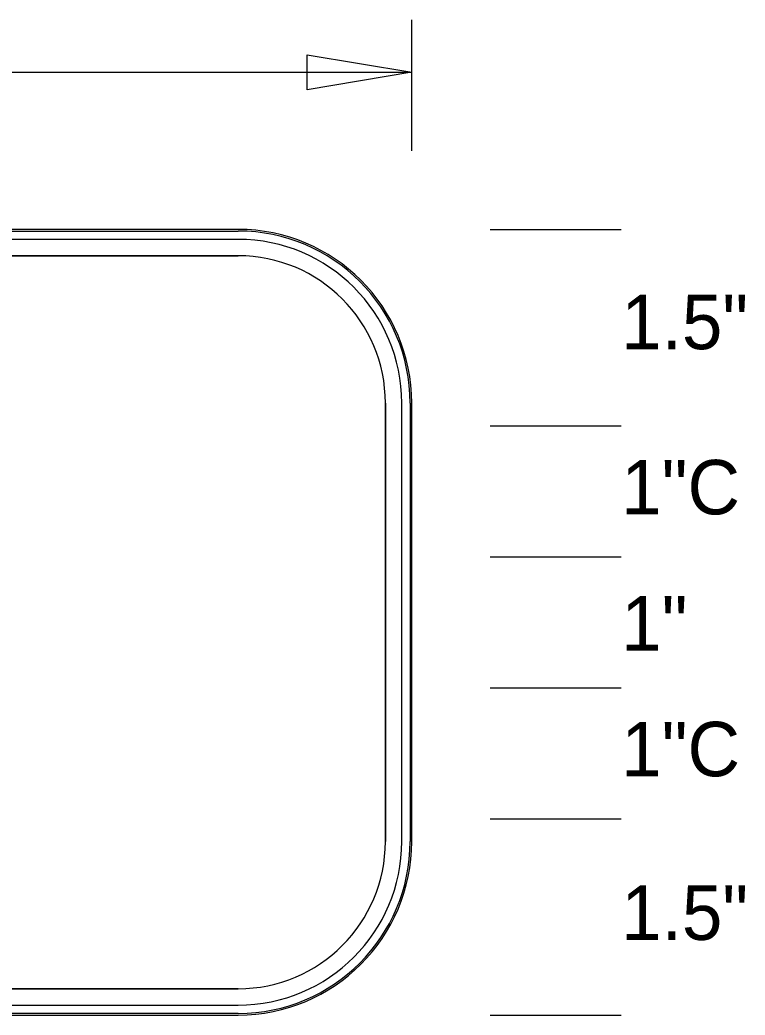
# Model space of a CAD drawing. Extents: x 0 to 770, y 0 to 495.
# Drawn here: x 700.7 to 747.3, y 409 to 473 of the extents above; entities that cross this region are included whole.
import ezdxf

# ---------------------------------------------------------------- set-up
doc = ezdxf.new("R2010")
doc.units = 0
for name, color, linetype in [('GSBWFill', 7, 'Continuous'), ('GSColorFill', 7, 'Continuous'), ('GSDims', 7, 'Continuous'), ('GSOutline', 7, 'Continuous')]:
    doc.layers.add(name, color=color, linetype=linetype)

msp = doc.modelspace()

# ---------------------------------------------------------------- linework, layer by layer
at = {"layer": 'GSBWFill'}
for p, q in [((714.711, 459.548), (636.008, 459.548)), ((714.711, 458.907), (636.008, 458.907)), ((636.008, 457.854), (714.711, 457.854)), ((724.182, 448.383), (724.182, 420.197)), ((725.235, 420.197), (725.235, 448.383)), ((725.876, 420.197), (725.876, 448.383)), ((714.711, 410.725), (636.019, 410.725)), ((636.019, 409.672), (714.711, 409.672)), ((636.008, 409.032), (714.711, 409.032))]:
    msp.add_line(p, q, dxfattribs=at)
for centre, radius, start, end in [((714.711, 448.383), 11.165, 0, 90), ((714.711, 448.383), 10.524, 0, 90), ((714.711, 448.383), 9.472, 0, 90), ((714.711, 420.197), 10.524, 270, 0), ((714.711, 420.197), 9.472, 270, 0), ((714.711, 420.197), 11.165, 270, 0)]:
    msp.add_arc(centre, radius, start, end, dxfattribs=at)
at = {"layer": 'GSColorFill'}
for p, q in [((714.711, 459.548), (636.008, 459.548)), ((714.711, 459.548), (636.008, 459.548)), ((636.008, 459.443), (714.711, 459.443)), ((714.711, 458.907), (636.008, 458.907)), ((636.008, 457.854), (714.711, 457.854)), ((724.182, 448.383), (724.182, 420.197)), ((725.235, 420.197), (725.235, 448.383)), ((725.771, 448.383), (725.771, 420.197)), ((725.876, 420.197), (725.876, 448.383)), ((725.876, 420.197), (725.876, 448.383)), ((714.711, 410.725), (636.019, 410.725)), ((636.019, 409.672), (714.711, 409.672)), ((636.008, 409.032), (714.711, 409.032)), ((714.711, 409.137), (636.009, 409.137)), ((636.009, 409.032), (714.711, 409.032))]:
    msp.add_line(p, q, dxfattribs=at)
for centre, radius, start, end in [((714.711, 448.383), 11.165, 0, 90), ((714.711, 448.383), 11.165, 0, 90), ((714.711, 448.383), 11.06, 0, 90), ((714.711, 448.383), 10.524, 0, 90), ((714.711, 448.383), 9.472, 0, 90), ((714.711, 420.197), 11.165, 270, 0), ((714.711, 420.197), 10.524, 270, 0), ((714.711, 420.197), 9.472, 270, 0), ((714.711, 420.197), 11.165, 270, 0), ((714.711, 420.197), 11.06, 270, 0)]:
    msp.add_arc(centre, radius, start, end, dxfattribs=at)
at = {"layer": 'GSDims'}
for p, q in [((725.876, 464.6), (725.876, 473.019)), ((624.843, 469.651), (725.876, 469.651)), ((730.928, 459.548), (739.347, 459.548)), ((730.928, 446.919), (739.347, 446.919)), ((730.928, 446.919), (739.347, 446.919)), ((730.928, 438.499), (739.347, 438.499)), ((730.928, 438.499), (739.347, 438.499)), ((730.928, 430.08), (739.347, 430.08)), ((730.928, 430.08), (739.347, 430.08)), ((730.928, 421.661), (739.347, 421.661)), ((730.928, 421.661), (739.347, 421.661)), ((730.928, 409.031), (739.347, 409.031))]:
    msp.add_line(p, q, dxfattribs=at)
msp.add_lwpolyline([(725.876, 469.651), (719.14, 468.529), (719.14, 470.774)], close=True, dxfattribs=at)
at = {"layer": 'GSOutline'}
for p, q in [((714.711, 459.548), (636.008, 459.548)), ((714.711, 458.907), (636.008, 458.907)), ((714.711, 457.854), (636.008, 457.854)), ((724.182, 420.197), (724.182, 448.383)), ((725.235, 420.197), (725.235, 448.383)), ((725.876, 420.197), (725.876, 448.383)), ((636.008, 410.725), (714.711, 410.725)), ((636.008, 409.672), (714.711, 409.672)), ((636.008, 409.032), (714.711, 409.032))]:
    msp.add_line(p, q, dxfattribs=at)
for centre, radius, start, end in [((714.711, 448.383), 11.165, 0, 90), ((714.711, 448.383), 10.524, 0, 90), ((714.711, 448.383), 9.472, 0, 90), ((714.711, 420.197), 10.524, 270, 0), ((714.711, 420.197), 9.472, 270, 0), ((714.711, 420.197), 11.165, 270, 0)]:
    msp.add_arc(centre, radius, start, end, dxfattribs=at)

# ---------------------------------------------------------------- texts
at = {"layer": 'GSDims'}
for s, p in [('1.5"', (739.347, 451.847)), ('1"C', (739.347, 441.226)), ('1"', (739.347, 432.47)), ('1"C', (739.347, 424.387)), ('1.5"', (739.347, 413.865))]:
    msp.add_text(s, height=3.5, dxfattribs=at).set_placement(p)

doc.saveas('drawing.dxf')
